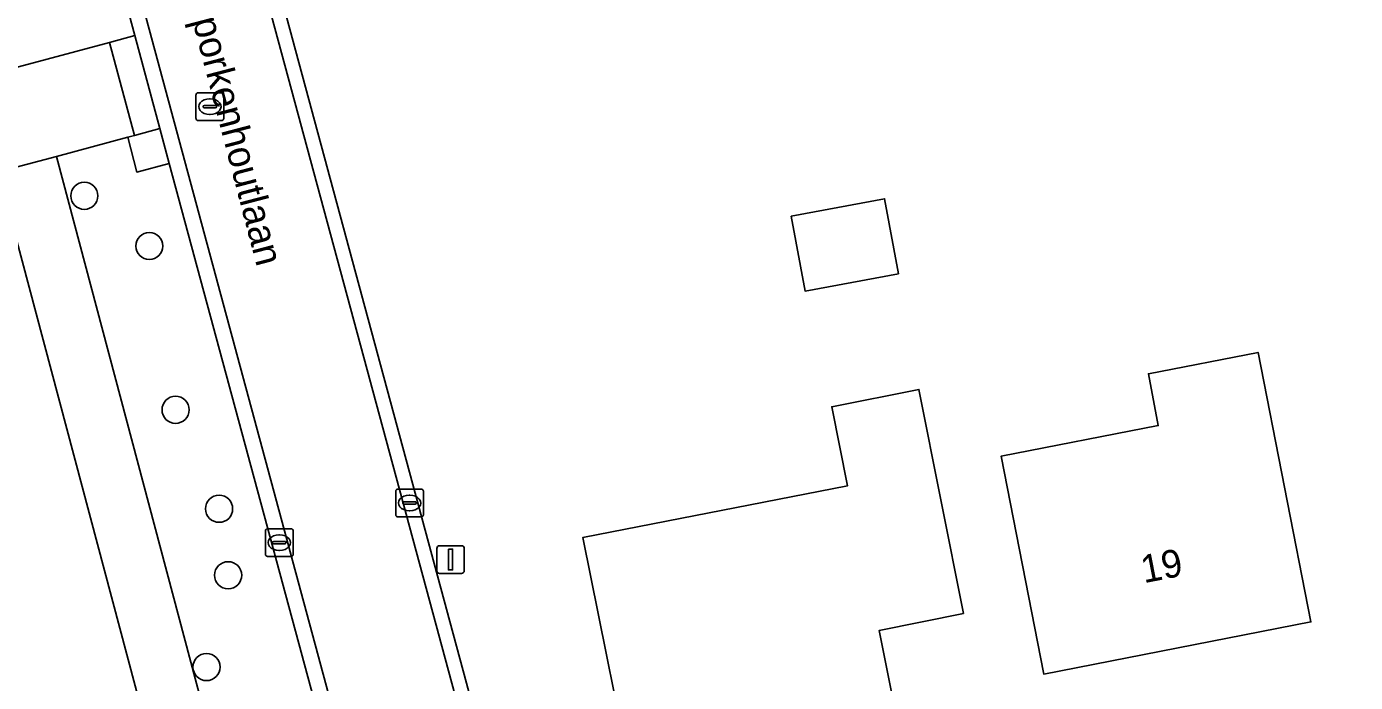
# Model space of a CAD drawing. Extents: x 162661 to 163484, y 380247 to 381230.
# Drawn here: x 162858.2 to 162906.07, y 380564.68 to 380588.32 of the extents above; entities that cross this region are included whole.
import ezdxf

# ---------------------------------------------------------------- set-up
doc = ezdxf.new("R2010")
doc.units = 0
for name, color, linetype in [('IMGEO_Berm_halfverhard', 7, 'Continuous'), ('IMGEO_Boom', 7, 'Continuous'), ('IMGEO_Erf', 7, 'Continuous'), ('IMGEO_Groenvoorziening', 7, 'Continuous'), ('IMGEO_Kolk', 7, 'Continuous'), ('IMGEO_Lichtmast', 7, 'Continuous'), ('IMGEO_Openbare_ruimte_label', 7, 'Continuous'), ('IMGEO_Pand', 7, 'Continuous'), ('IMGEO_Pand_nummerreeks', 7, 'Continuous'), ('IMGEO_Parkeervlak_open', 7, 'Continuous'), ('IMGEO_Rijbaan_lokaal_gesloten', 7, 'Continuous'), ('IMGEO_Rijbaan_lokaal_open', 7, 'Continuous'), ('IMGEO_Rioolput', 7, 'Continuous'), ('IMGEO_Voetpad_open', 7, 'Continuous')]:
    doc.layers.add(name, color=color, linetype=linetype)

msp = doc.modelspace()

# ---------------------------------------------------------------- linework, layer by layer
at = {"layer": 'IMGEO_Berm_halfverhard'}
msp.add_lwpolyline([(162862.997, 380584.64), (162862.089, 380584.396), (162861.845, 380584.331), (162862.17, 380583.075), (162863.335, 380583.384)], close=True, dxfattribs=at)
at = {"layer": 'IMGEO_Boom'}
for centre in [(162860.279, 380582.22), (162862.621, 380580.41), (162863.567, 380574.505), (162865.134, 380570.938), (162865.46, 380568.541), (162864.683, 380565.232)]:
    msp.add_circle(centre, 0.489, dxfattribs=at)
at = {"layer": 'IMGEO_Erf'}
for points in [[(162928.422, 380628.58), (162922.445, 380627.013), (162924.514, 380620.67), (162904.943, 380613.922), (162874.152, 380603.239), (162872.455, 380602.652), (162865.273, 380600.713), (162864.386, 380600.474), (162876.183, 380556.737), (162876.524, 380555.474), (162877.407, 380555.713), (162877.661, 380555.782), (162884.529, 380557.64), (162887.699, 380558.228), (162916.304, 380563.813), (162938.452, 380568.15), (162939.612, 380563.204), (162949.689, 380565.695)], [(162885.744, 380581.487), (162889.111, 380582.111), (162889.611, 380579.41), (162886.244, 380578.787)], [(162904.468, 380566.86), (162894.843, 380564.978), (162893.308, 380572.829), (162898.971, 380573.937), (162898.613, 380575.803), (162902.568, 380576.576)], [(162891.958, 380567.159), (162888.918, 380566.553), (162889.315, 380564.562), (162889.829, 380561.983), (162880.225, 380560.068), (162878.237, 380569.899), (162887.775, 380571.77), (162887.208, 380574.614), (162890.347, 380575.24)]]:
    msp.add_lwpolyline(points, close=True, dxfattribs=at)
msp.add_lwpolyline([(162827.542, 380524.495), (162863.528, 380536.977), (162867.163, 380537.953), (162869.049, 380538.459), (162868.949, 380538.835), (162857.178, 380583.078)], dxfattribs=at)
at = {"layer": 'IMGEO_Groenvoorziening'}
msp.add_lwpolyline([(162859.28, 380583.642), (162870.993, 380539.488), (162871.119, 380539.015), (162873.866, 380539.752), (162873.529, 380541.018), (162874.697, 380541.306), (162863.335, 380583.384), (162862.17, 380583.075), (162861.845, 380584.331)], close=True, dxfattribs=at)
at = {"layer": 'IMGEO_Kolk'}
for p, q in [((162871.572, 380571.647), (162872.424, 380571.647)), ((162871.497, 380570.721), (162871.497, 380571.573)), ((162871.756, 380571.141), (162871.756, 380571.153)), ((162871.799, 380571.19), (162872.197, 380571.19)), ((162871.985, 380571.427), (162872.01, 380571.427)), ((162872.24, 380571.153), (162872.24, 380571.141)), ((162872.498, 380571.573), (162872.498, 380570.721)), ((162872.194, 380571.104), (162871.796, 380571.104)), ((162872.008, 380570.867), (162871.983, 380570.867)), ((162866.878, 380570.218), (162867.73, 380570.218)), ((162872.424, 380570.647), (162871.572, 380570.647)), ((162866.803, 380569.292), (162866.803, 380570.144)), ((162867.062, 380569.712), (162867.062, 380569.724)), ((162867.105, 380569.761), (162867.503, 380569.761)), ((162867.291, 380569.998), (162867.316, 380569.998)), ((162867.546, 380569.724), (162867.546, 380569.712)), ((162867.804, 380570.144), (162867.804, 380569.292)), ((162867.5, 380569.675), (162867.102, 380569.675)), ((162867.314, 380569.438), (162867.289, 380569.438)), ((162867.73, 380569.218), (162866.878, 380569.218))]:
    msp.add_line(p, q, dxfattribs=at)
for points in [[(162871.572, 380571.647), (162872.424, 380571.647)], [(162871.497, 380570.721), (162871.497, 380571.573)], [(162872.498, 380571.573), (162872.498, 380570.721)], [(162866.878, 380570.218), (162867.73, 380570.218)], [(162872.424, 380570.647), (162871.572, 380570.647)], [(162866.803, 380569.292), (162866.803, 380570.144)], [(162867.804, 380570.144), (162867.804, 380569.292)], [(162867.73, 380569.218), (162866.878, 380569.218)]]:
    msp.add_lwpolyline(points, dxfattribs=at)
for centre, radius, start, end in [((162871.574, 380571.571), 0.0765, 91.552, 178.448), ((162871.574, 380571.571), 0.0765, 91.552, 178.448), ((162872.422, 380571.571), 0.0765, 1.552, 88.448), ((162872.422, 380571.571), 0.0765, 1.552, 88.448), ((162871.796, 380571.15), 0.0403, 85.8775, 175.7526), ((162871.793, 380571.14), 0.0366, 178.938, 274.7102), ((162872.197, 380571.147), 0.043, 264.8664, 352.4533), ((162872.201, 380571.152), 0.0386, 1.7309, 96.639), ((162871.574, 380570.723), 0.0765, 181.552, 268.448), ((162871.574, 380570.723), 0.0765, 181.552, 268.448), ((162872.422, 380570.723), 0.0765, 271.552, 358.448), ((162872.422, 380570.723), 0.0765, 271.552, 358.448), ((162866.88, 380570.142), 0.0765, 91.552, 178.448), ((162866.88, 380570.142), 0.0765, 91.552, 178.448), ((162867.728, 380570.142), 0.0765, 1.552, 88.448), ((162867.728, 380570.142), 0.0765, 1.552, 88.448), ((162867.102, 380569.721), 0.0403, 85.8775, 175.7526), ((162867.099, 380569.711), 0.0366, 178.938, 274.7102), ((162867.503, 380569.718), 0.043, 264.8664, 352.4533), ((162867.507, 380569.723), 0.0386, 1.7309, 96.639), ((162866.88, 380569.294), 0.0765, 181.552, 268.448), ((162866.88, 380569.294), 0.0765, 181.552, 268.448), ((162867.728, 380569.294), 0.0765, 271.552, 358.448), ((162867.728, 380569.294), 0.0765, 271.552, 358.448)]:
    msp.add_arc(centre, radius, start, end, dxfattribs=at)
for centre, major_axis, ratio, start_param, end_param in [((162871.984, 380571.147), (-0.387, 0.002), 0.722429, 4.712389, 7.853982), ((162872.009, 380571.147), (-0.39, 0.002), 0.717154, 1.570796, 4.712389), ((162867.29, 380569.718), (-0.387, 0.002), 0.722429, 4.712389, 7.853982), ((162867.315, 380569.718), (-0.39, 0.002), 0.717154, 1.570796, 4.712389)]:
    msp.add_ellipse(centre, major_axis=major_axis, ratio=ratio, start_param=start_param, end_param=end_param, dxfattribs=at)
at = {"layer": 'IMGEO_Lichtmast'}
for p, q in [((162872.979, 380568.707), (162872.979, 380569.507)), ((162872.979, 380569.507), (162872.979, 380568.707)), ((162873.079, 380569.607), (162873.869, 380569.607)), ((162873.869, 380569.607), (162873.079, 380569.607)), ((162873.969, 380569.507), (162873.969, 380568.707)), ((162873.969, 380568.707), (162873.969, 380569.507)), ((162873.869, 380568.607), (162873.079, 380568.607)), ((162873.079, 380568.607), (162873.869, 380568.607))]:
    msp.add_line(p, q, dxfattribs=at)
msp.add_lwpolyline([(162873.399, 380569.482), (162873.549, 380569.482), (162873.549, 380568.732), (162873.399, 380568.732), (162873.399, 380569.482)], dxfattribs=at)
for centre, start, end in [((162873.079, 380569.507), 90, 180), ((162873.079, 380569.507), 90, 180), ((162873.869, 380569.507), 0, 90), ((162873.869, 380569.507), 360, 90), ((162873.079, 380568.707), 180, 270), ((162873.079, 380568.707), 180, 270), ((162873.869, 380568.707), 270, 0), ((162873.869, 380568.707), 270, 0)]:
    msp.add_arc(centre, 0.1, start, end, dxfattribs=at)
at = {"layer": 'IMGEO_Pand'}
for points in [[(162885.744, 380581.487), (162886.244, 380578.787), (162889.611, 380579.41), (162889.111, 380582.111)], [(162894.843, 380564.978), (162904.468, 380566.86), (162902.568, 380576.576), (162898.613, 380575.803), (162898.971, 380573.937), (162893.308, 380572.829)], [(162891.958, 380567.159), (162890.347, 380575.24), (162887.208, 380574.614), (162887.775, 380571.77), (162878.237, 380569.899), (162880.225, 380560.068), (162889.829, 380561.983), (162889.315, 380564.562), (162888.918, 380566.553)]]:
    msp.add_lwpolyline(points, close=True, dxfattribs=at)
at = {"layer": 'IMGEO_Parkeervlak_open'}
msp.add_lwpolyline([(162857.351, 380602.071), (162850.454, 380600.2), (162854.145, 380586.31), (162854.256, 380585.892), (162861.186, 380587.749), (162862.096, 380587.993), (162858.243, 380602.314)], close=True, dxfattribs=at)
at = {"layer": 'IMGEO_Rijbaan_lokaal_gesloten'}
msp.add_lwpolyline([(162889.085, 380501.285), (162890.125, 380503.167), (162886.907, 380515.067), (162864.293, 380598.811), (162858.479, 380620.583), (162847.107, 380663.14), (162842.816, 380661.994), (162845.2, 380653.071), (162853.834, 380620.756), (162875.558, 380540.207), (162882.977, 380512.698), (162884.78, 380511.647)], dxfattribs=at)
at = {"layer": 'IMGEO_Rijbaan_lokaal_open'}
for points in [[(162847.73, 380662.896), (162847.622, 380663.278), (162847.107, 380663.14), (162858.479, 380620.583), (162864.293, 380598.811), (162886.907, 380515.067), (162890.125, 380503.167)], [(162890.292, 380504.561), (162887.4, 380515.173), (162881.586, 380536.716), (162880.645, 380540.205), (162877.424, 380552.141), (162876.524, 380555.474), (162876.183, 380556.737), (162864.386, 380600.474), (162863.498, 380603.804), (162860.275, 380615.873), (162859.381, 380619.222), (162859.045, 380620.483), (162859.007, 380620.625), (162858.095, 380624.087), (162852.737, 380643.9), (162847.73, 380662.896)], [(162849.741, 380633.782), (162853.306, 380620.608), (162857.003, 380606.907), (162857.345, 380605.64), (162858.243, 380602.314), (162862.096, 380587.993), (162862.997, 380584.64), (162863.335, 380583.384), (162874.697, 380541.306), (162875.032, 380540.065), (162875.558, 380540.207), (162853.834, 380620.756), (162845.2, 380653.071)]]:
    msp.add_lwpolyline(points, dxfattribs=at)
at = {"layer": 'IMGEO_Rioolput'}
for p, q in [((162864.302, 380585.006), (162864.302, 380585.858)), ((162864.377, 380585.932), (162865.229, 380585.932)), ((162864.79, 380585.712), (162864.815, 380585.712)), ((162865.303, 380585.858), (162865.303, 380585.006)), ((162864.561, 380585.426), (162864.561, 380585.438)), ((162864.999, 380585.389), (162864.601, 380585.389)), ((162864.604, 380585.475), (162865.002, 380585.475)), ((162864.813, 380585.152), (162864.788, 380585.152)), ((162865.045, 380585.438), (162865.045, 380585.426)), ((162865.229, 380584.932), (162864.377, 380584.932))]:
    msp.add_line(p, q, dxfattribs=at)
for points in [[(162864.302, 380585.006), (162864.302, 380585.858)], [(162864.377, 380585.932), (162865.229, 380585.932)], [(162865.303, 380585.858), (162865.303, 380585.006)], [(162865.229, 380584.932), (162864.377, 380584.932)]]:
    msp.add_lwpolyline(points, dxfattribs=at)
for centre, radius, start, end in [((162864.379, 380585.856), 0.0765, 91.552, 178.448), ((162864.379, 380585.856), 0.0765, 91.552, 178.448), ((162865.227, 380585.856), 0.0765, 1.552, 88.448), ((162865.227, 380585.856), 0.0765, 1.552, 88.448), ((162864.601, 380585.435), 0.0403, 85.8775, 175.7526), ((162864.598, 380585.425), 0.0366, 178.938, 274.7102), ((162865.002, 380585.432), 0.043, 264.8664, 352.4533), ((162865.006, 380585.437), 0.0386, 1.7309, 96.639), ((162864.379, 380585.008), 0.0765, 181.552, 268.448), ((162864.379, 380585.008), 0.0765, 181.552, 268.448), ((162865.227, 380585.008), 0.0765, 271.552, 358.448), ((162865.227, 380585.008), 0.0765, 271.552, 358.448)]:
    msp.add_arc(centre, radius, start, end, dxfattribs=at)
for centre, major_axis, ratio, start_param, end_param in [((162864.789, 380585.432), (-0.387, 0.002), 0.722429, 4.712389, 7.853982), ((162864.814, 380585.432), (-0.39, 0.002), 0.717154, 1.570796, 4.712389)]:
    msp.add_ellipse(centre, major_axis=major_axis, ratio=ratio, start_param=start_param, end_param=end_param, dxfattribs=at)
at = {"layer": 'IMGEO_Voetpad_open'}
for points in [[(162862.089, 380584.396), (162862.997, 380584.64), (162862.096, 380587.993), (162861.186, 380587.749)], [(162859.28, 380583.642), (162861.845, 380584.331), (162862.089, 380584.396), (162861.186, 380587.749), (162854.256, 380585.892), (162855.09, 380582.837), (162855.172, 380582.539), (162857.178, 380583.078)], [(162859.28, 380583.642), (162857.178, 380583.078), (162868.949, 380538.835), (162869.049, 380538.459), (162871.119, 380539.015), (162870.993, 380539.488)]]:
    msp.add_lwpolyline(points, close=True, dxfattribs=at)

# ---------------------------------------------------------------- texts
at = {"layer": 'IMGEO_Openbare_ruimte_label'}
msp.add_text('Sporkenhoutlaan', height=1, rotation=284.6619, dxfattribs=at).set_placement((162863.941, 380589.409))
at = {"layer": 'IMGEO_Pand_nummerreeks'}
msp.add_text('19', height=1, rotation=11.0636, dxfattribs=at).set_placement((162898.451, 380568.251))

doc.saveas('drawing.dxf')
